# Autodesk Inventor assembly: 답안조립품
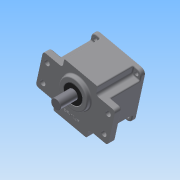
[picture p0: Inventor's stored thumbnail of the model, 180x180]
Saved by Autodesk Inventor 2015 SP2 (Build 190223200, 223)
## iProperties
Created: 2015-06
Part Number: 답안조립품
Document SubType Name: Assembly
Designer: AMC
Author: AMC
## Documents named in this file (12)
- C:\Users\AMC\Desktop\450620V1013\답안조립품.iam
- C:\Users\AMC\Desktop\450620V1013\본체.ipt
- C:\Users\AMC\Desktop\450620V1013\오일실 17x32x8.ipt
- C:\Users\AMC\Desktop\450620V1013\베어링 6003.ipt
- 베어링 6003.ipt
- C:\Users\AMC\Desktop\450620V1013\베어링 608.ipt
- 베어링 608.ipt
- C:\Users\AMC\Desktop\450620V1013\서브축.ipt
- C:\Users\AMC\Desktop\450620V1013\메인축.ipt
- C:\Users\AMC\Desktop\450620V1013\커버.ipt
- C:\Users\AMC\Desktop\450620V1013\오일실 8x22x7.ipt
- C:\Users\AMC\Desktop\450620V1013\M4x0.5x16.ipt
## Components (4 placed, 1 different names)
1. M4x0.5x12:1
2. M4x0.5x12:2
3. M4x0.5x12:3
4. M4x0.5x12:4
